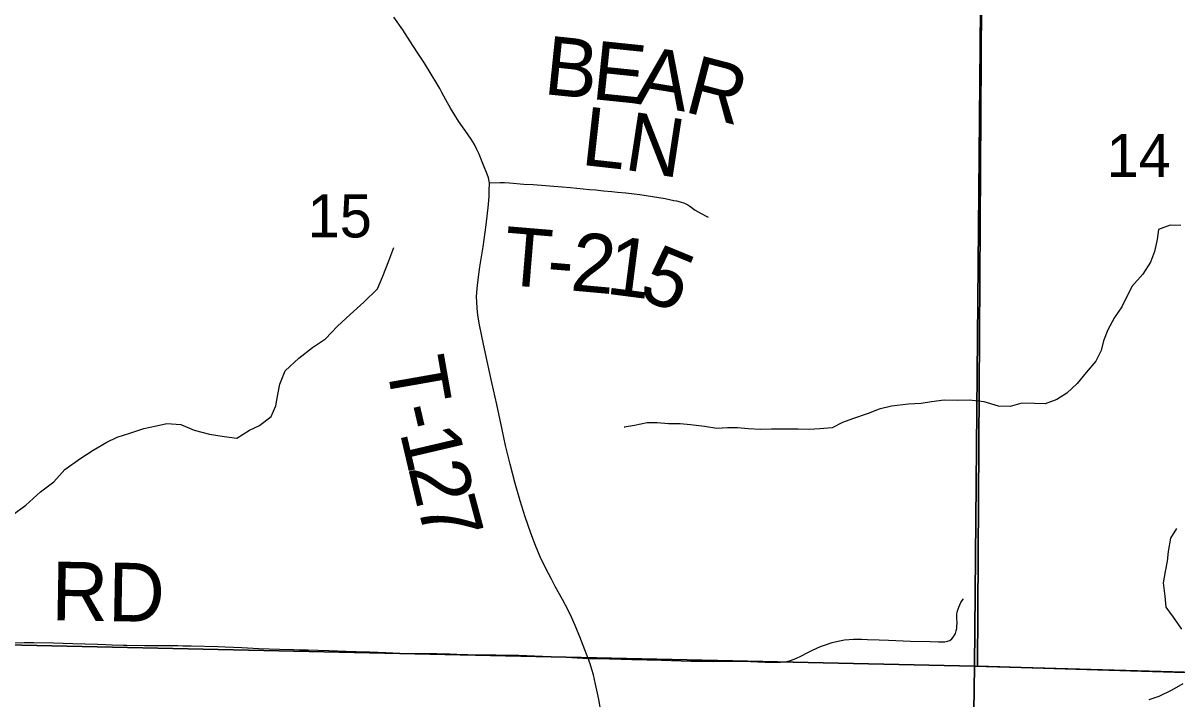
# Model space of a CAD drawing. Extents: x 0 to 34, y 0 to 22.
# Drawn here: x 24.137 to 25.255, y 17.712 to 18.367 of the extents above; entities that cross this region are included whole.
import ezdxf

# ---------------------------------------------------------------- set-up
doc = ezdxf.new("R2010")
doc.units = 0
for name, color, linetype in [('GM_X_Corporation', 7, 'Continuous'), ('GM_X_Minor_River', 7, 'Continuous'), ('GM_X_Section_Text', 7, 'Continuous'), ('GM_X_Township_Road', 7, 'Continuous'), ('GM_X_Township_Road_Text', 7, 'Continuous')]:
    doc.layers.add(name, color=color, linetype=linetype)

msp = doc.modelspace()

# ---------------------------------------------------------------- linework, layer by layer
at = {"layer": 'GM_X_Corporation'}
for points in [[(30.3167, 20.9), (25.1014, 20.9), (25.0988, 20.7425), (25.0847, 19.8351), (25.0701, 18.7696), (25.0668, 18.5474), (25.0619, 17.7438), (25.4012, 17.7333), (26.0747, 17.7146), (26.0759, 17.6934), (26.0745, 17.4524), (26.0677, 16.948), (26.0646, 16.863), (26.0683, 16.6823), (26.3378, 16.673), (27.0694, 16.6556)], [(26.0759, 17.6934), (26.0747, 17.7146), (25.4012, 17.7333), (25.0619, 17.7438), (25.0668, 18.5474), (25.0701, 18.7696), (25.0847, 19.8351), (25.0988, 20.7425), (24.9808, 20.7443), (24.1323, 20.7702), (24.1208, 20.7707), (23.5167, 20.7862), (23.5167, 14.7114)]]:
    msp.add_lwpolyline(points, dxfattribs=at)
for points in [[(25.0685, 18.7697), (25.0591, 17.7438), (24.0329, 17.7663), (24.0555, 18.7938)], [(26.0916, 18.7368), (26.075, 17.7146), (25.0591, 17.7438), (25.0685, 18.7697)], [(24.0329, 17.7663), (25.0591, 17.7438), (25.0442, 16.7237), (24.0196, 16.7435)], [(26.075, 17.7146), (26.0652, 16.6798), (25.0442, 16.7237), (25.0591, 17.7438)]]:
    msp.add_lwpolyline(points, close=True, dxfattribs=at)
at = {"layer": 'GM_X_Minor_River'}
for points in [[(25.2591, 18.1708), (25.2485, 18.1711), (25.2372, 18.1668), (25.2361, 18.157), (25.2336, 18.1456), (25.2295, 18.1353), (25.2221, 18.1235), (25.2116, 18.1116), (25.2019, 18.0918), (25.1948, 18.0815), (25.1881, 18.0697), (25.1841, 18.059), (25.1819, 18.0495), (25.1767, 18.0393), (25.1673, 18.0282), (25.1584, 18.0175), (25.1486, 18.0083), (25.1388, 18.0021), (25.1275, 17.9978), (25.1173, 17.9981), (25.1048, 17.9984), (25.0935, 17.9952), (25.0822, 17.9955), (25.0685, 17.9999), (25.0538, 18.0016), (25.0424, 18.0011), (25.0296, 18.0014), (25.0175, 17.9997), (25.0073, 17.9981), (24.9952, 17.9976), (24.9786, 17.9955), (24.9665, 17.9927), (24.956, 17.9885), (24.9409, 17.9834), (24.9311, 17.9799), (24.921, 17.9745), (24.9092, 17.9736), (24.8987, 17.9731), (24.8881, 17.9734), (24.8752, 17.9732), (24.8624, 17.9735), (24.8518, 17.973), (24.8397, 17.9736), (24.8298, 17.9746), (24.8196, 17.9745), (24.8094, 17.974), (24.7973, 17.9758), (24.7837, 17.9776), (24.7739, 17.9786), (24.7625, 17.9785), (24.7516, 17.9795), (24.7417, 17.9794), (24.7297, 17.977), (24.7195, 17.9754), (24.7198, 17.9754)], [(24.1265, 17.8899), (24.1397, 17.8998), (24.154, 17.9125), (24.1668, 17.9224), (24.1777, 17.9343), (24.192, 17.9446), (24.2049, 17.953), (24.2181, 17.9607), (24.2283, 17.9657), (24.2404, 17.9696), (24.254, 17.9739), (24.2665, 17.9766), (24.2764, 17.979), (24.29, 17.9779), (24.3029, 17.9723), (24.3177, 17.9686), (24.3318, 17.9664), (24.3443, 17.9646), (24.3564, 17.9723), (24.3662, 17.9769), (24.3775, 17.9857), (24.382, 17.996), (24.3838, 18.007), (24.386, 18.0169), (24.3909, 18.0298), (24.4044, 18.0421), (24.4176, 18.0524), (24.4301, 18.0608), (24.4418, 18.0731), (24.4542, 18.0845), (24.4674, 18.0964), (24.4806, 18.1094), (24.4858, 18.1216), (24.4914, 18.1364), (24.4962, 18.1494)], [(25.2598, 17.7795), (25.2518, 17.7911), (25.2449, 17.8009), (25.2437, 17.8115), (25.2421, 17.8244), (25.2442, 17.8354), (25.246, 17.8453), (25.2471, 17.8547), (25.2492, 17.8676), (25.2552, 17.8772)], [(25.2283, 17.7113), (25.2381, 17.7148), (25.2505, 17.7207), (25.2611, 17.7268)]]:
    msp.add_lwpolyline(points, dxfattribs=at)
at = {"layer": 'GM_X_Township_Road'}
for points in [[(24.589, 18.2121), (24.5881, 18.2169), (24.5868, 18.2205), (24.5834, 18.2291), (24.5813, 18.2341), (24.579, 18.2398), (24.5769, 18.2443), (24.5744, 18.2493), (24.5712, 18.2545), (24.5684, 18.2586), (24.5655, 18.2626), (24.563, 18.2662), (24.5591, 18.2718), (24.5554, 18.2775), (24.5512, 18.2843), (24.5466, 18.2924), (24.5428, 18.2996), (24.5408, 18.3034), (24.538, 18.3082), (24.5325, 18.3173), (24.526, 18.3279), (24.5197, 18.3378), (24.5149, 18.3451), (24.505, 18.3602), (24.4965, 18.3724)], [(24.6847, 17.7511), (24.6765, 17.7722), (24.6721, 17.7832), (24.6685, 17.7912), (24.6653, 17.7979), (24.6598, 17.8083), (24.6528, 17.8208), (24.649, 17.8279), (24.6434, 17.839), (24.6383, 17.8496), (24.6337, 17.8605), (24.629, 17.8727), (24.6236, 17.8885), (24.6187, 17.9039), (24.6139, 17.9207), (24.6091, 17.9393), (24.6047, 17.9574), (24.6012, 17.9731), (24.5962, 17.9974), (24.5914, 18.0186), (24.5867, 18.0392), (24.5832, 18.0556), (24.5794, 18.0745), (24.5778, 18.0837), (24.577, 18.0905), (24.5767, 18.0967), (24.5766, 18.1016), (24.5771, 18.1097), (24.5784, 18.1208), (24.5798, 18.1305), (24.5813, 18.1402), (24.5829, 18.1499), (24.5859, 18.1714), (24.5882, 18.1911), (24.5888, 18.1992), (24.5888, 18.2041), (24.589, 18.2121)], [(24.589, 18.2121), (24.599, 18.2124), (24.6036, 18.2124), (24.6086, 18.212), (24.6222, 18.2108), (24.6315, 18.2103), (24.6513, 18.2087), (24.6674, 18.2074), (24.6736, 18.2068), (24.6859, 18.2057), (24.6921, 18.2051), (24.6995, 18.2043), (24.7076, 18.2035), (24.7131, 18.203), (24.7211, 18.2022), (24.7292, 18.2013), (24.7347, 18.2006), (24.7409, 18.1999), (24.747, 18.1989), (24.7531, 18.1979), (24.7592, 18.1967), (24.7678, 18.195), (24.7702, 18.1945), (24.7738, 18.1937), (24.778, 18.1924), (24.7813, 18.1908), (24.7833, 18.1894), (24.7883, 18.1856), (24.7942, 18.1822), (24.7996, 18.1793), (24.8008, 18.1788)], [(24.6847, 17.7511), (24.6955, 17.751), (24.7054, 17.7508), (24.7166, 17.7505), (24.7271, 17.7502), (24.7557, 17.7494), (24.7842, 17.7486), (24.796, 17.7484), (24.8065, 17.7483), (24.814, 17.7484), (24.8349, 17.7485), (24.8563, 17.7477), (24.8655, 17.7475), (24.871, 17.7475), (24.8753, 17.748), (24.8782, 17.7486), (24.8807, 17.7492), (24.8859, 17.7511), (24.8915, 17.7538), (24.897, 17.7565), (24.902, 17.7591), (24.9099, 17.7627), (24.9145, 17.7645), (24.921, 17.7667), (24.9282, 17.7683), (24.9331, 17.7691), (24.9417, 17.7699), (24.9498, 17.7699), (24.9554, 17.7697), (24.9665, 17.7693), (24.9758, 17.7689), (24.9969, 17.768), (25.0162, 17.7675), (25.0243, 17.7672), (25.0274, 17.7672), (25.0304, 17.7674), (25.033, 17.7678), (25.0352, 17.7687), (25.0371, 17.7701), (25.0385, 17.7717), (25.0398, 17.7736), (25.0406, 17.7754), (25.0413, 17.7778), (25.0418, 17.7801), (25.042, 17.782), (25.0421, 17.7857), (25.0419, 17.7901), (25.0419, 17.7932), (25.042, 17.7945), (25.0422, 17.7956), (25.0427, 17.7974), (25.0438, 17.8008), (25.0448, 17.8031), (25.0459, 17.8054), (25.0471, 17.8074), (25.0483, 17.8088)], [(24.1214, 17.7664), (24.1381, 17.7665), (24.1474, 17.7665), (24.1667, 17.7662), (24.1853, 17.7658), (24.197, 17.7654), (24.2094, 17.7649), (24.2173, 17.7646), (24.2234, 17.7643), (24.2345, 17.7641), (24.2375, 17.764), (24.2548, 17.7638), (24.2634, 17.7638), (24.2782, 17.7638), (24.2869, 17.7637), (24.2919, 17.7635), (24.3, 17.7633), (24.326, 17.7629), (24.3329, 17.7626), (24.349, 17.7617), (24.3657, 17.7609), (24.3856, 17.7602), (24.3992, 17.7597), (24.4048, 17.7596), (24.4129, 17.7594), (24.4228, 17.7591), (24.4333, 17.7589), (24.4501, 17.7582), (24.46, 17.7579), (24.473, 17.7575), (24.4885, 17.7569), (24.5022, 17.7564), (24.5208, 17.756), (24.5331, 17.756), (24.5381, 17.7559), (24.5455, 17.7557), (24.5505, 17.7555), (24.5573, 17.7552), (24.579, 17.7548), (24.5951, 17.7546), (24.6174, 17.7543), (24.6633, 17.7524), (24.6847, 17.7511)], [(24.6924, 17.6002), (24.6947, 17.6178), (24.6959, 17.6283), (24.6974, 17.643), (24.6982, 17.6548), (24.6989, 17.6647), (24.6991, 17.6777), (24.6988, 17.6829), (24.6985, 17.6877), (24.6979, 17.6938), (24.6964, 17.7036), (24.6953, 17.7097), (24.6943, 17.7146), (24.6917, 17.7262), (24.6897, 17.7352), (24.6882, 17.7406), (24.6865, 17.7459), (24.6847, 17.7511)]]:
    msp.add_lwpolyline(points, dxfattribs=at)

# ---------------------------------------------------------------- texts
at = {"layer": 'GM_X_Section_Text'}
for s, p in [('14', (25.187, 18.2176)), ('15', (24.4128, 18.1591))]:
    msp.add_text(s, height=0.04186, rotation=0, dxfattribs=at).set_placement(p)
at = {"layer": 'GM_X_Township_Road_Text'}
for s, height, rotation, p in [('B', 0.0568, 354.1038, (24.6406, 18.2982)), ('E', 0.0568, 354.1046, (24.687, 18.2934)), ('A', 0.0568, 350.6754, (24.7284, 18.2891)), ('R', 0.0568, 345.3854, (24.7764, 18.2813)), ('L', 0.0568, 353.6548, (24.6769, 18.2296)), ('N', 0.0568, 351.2929, (24.7185, 18.225)), ('T', 0.0568, 355.2549, (24.6011, 18.1134)), ('2', 0.0568, 354.8072, (24.6666, 18.1079)), ('1', 0.0568, 352.6471, (24.7009, 18.1048)), ('5', 0.0568, 337.6536, (24.7318, 18.1014)), ('-', 0.0568, 355.1819, (24.6434, 18.1099)), ('T', 0.0568, 279.9714, (24.4886, 18.0384)), ('-', 0.0568, 283.2033, (24.4966, 17.9931)), ('1', 0.0568, 283.1887, (24.502, 17.9704)), ('2', 0.0568, 283.4081, (24.51, 17.9361)), ('7', 0.0568, 284.9397, (24.5185, 17.9004)), ('RD', 0.05682, 359.024, (24.1642, 17.7883))]:
    msp.add_text(s, height=height, rotation=rotation, dxfattribs=at).set_placement(p)

doc.saveas('drawing.dxf')
